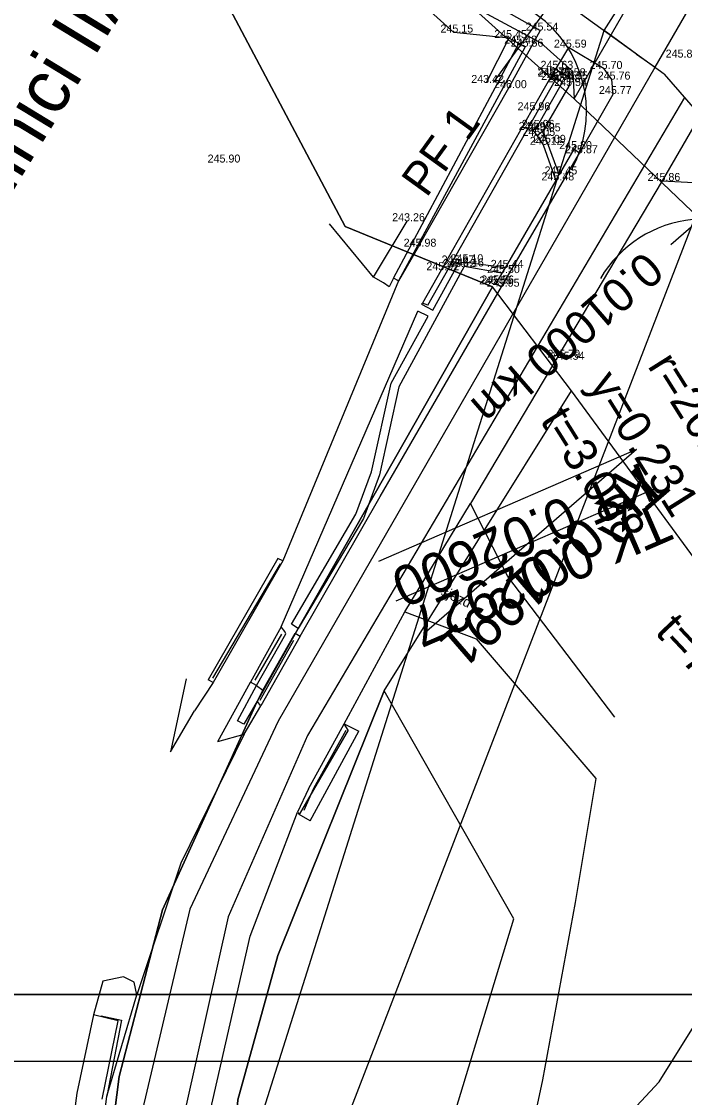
# Model space of a CAD drawing. Extents: x -555887 to -552101, y -1100251 to -1096546.
# Drawn here: x -554080.2 to -554030.5, y -1097398.4 to -1097317.8 of the extents above; entities that cross this region are included whole.
import ezdxf

# ---------------------------------------------------------------- set-up
doc = ezdxf.new("R2010")
doc.units = 0
for name, color, linetype in [('PARCELY_cesty', 7, 'Continuous'), ('PARCELY_silnice', 7, 'Continuous'), ('PARCELY_VHO', 7, 'Continuous'), ('POLYGONY_rozšíření', 7, 'Continuous'), ('POLYGONY_SITUACE_PF', 7, 'Continuous'), ('POLYGONY_SITUACE_PF_POPISY', 7, 'Continuous'), ('POLYGONY_SITUACE_PO', 7, 'Continuous'), ('ram_VC6', 7, 'Continuous'), ('ROZHLED_parcela_cesty', 7, 'Continuous'), ('ROZHLED_ram_legenda_1', 7, 'Continuous'), ('ROZHLED_ram_legenda_2', 7, 'Continuous'), ('ROZHLED_trojuhelniky_1', 7, 'Continuous'), ('ROZHLED_trojuhelniky_2', 7, 'Continuous'), ('vrstevnice', 7, 'Continuous'), ('Výškopis', 7, 'Continuous'), ('ZSST', 7, 'Continuous'), ('zájem', 7, 'Continuous')]:
    doc.layers.add(name, color=color, linetype=linetype)

msp = doc.modelspace()

# ---------------------------------------------------------------- linework, layer by layer
for p, q in [((-554034.06, -1097349.842), (-554053.407, -1097358.241)), ((-554034.06, -1097349.842), (-554050, -1097363.654)), ((-554032.76, -1097352.836), (-554052.107, -1097361.236))]:
    msp.add_line(p, q)
at = {"layer": 'PARCELY_cesty'}
msp.add_lwpolyline([(-554038.74, -1097323.54), (-554046.65, -1097316.45), (-554056.115, -1097302.24), (-554073.622, -1097267.292), (-554075.994, -1097261.695), (-554077.187, -1097257.67), (-554078.248, -1097251.684), (-554079.797, -1097235.406), (-554080.53, -1097230.23), (-554082.571, -1097222.628), (-554085.074, -1097216.125), (-554088.037, -1097210.809), (-554104.663, -1097183.794), (-554111.367, -1097172.04), (-554117.392, -1097160.013), (-554120.974, -1097151.787), (-554130.309, -1097129.113)], dxfattribs=at)
at = {"layer": 'PARCELY_silnice'}
msp.add_lwpolyline([(-553831.55, -1096945.97), (-553822.14, -1096946.52), (-553820.19, -1096947.25), (-553823.19, -1096962.08), (-553832.13, -1096986.8), (-553848.04, -1097015.24), (-554028.81, -1097333.03), (-554038.74, -1097323.54), (-553856.4, -1097007.66), (-553843.04, -1096981.51), (-553834.33, -1096958.81)], close=True, dxfattribs=at)
msp.add_lwpolyline([(-554030.91, -1097678.33), (-554047.02, -1097559.88), (-554049.28, -1097545.25), (-554058.01, -1097480.43), (-554064.42, -1097434.91), (-554064.99, -1097411.72), (-554063.97, -1097398.61), (-554060.96, -1097387.79), (-554052.99, -1097367.96), (-554038.93, -1097345.45), (-554044.87, -1097337.64), (-554059.66, -1097363.67), (-554062.54, -1097368.79), (-554069.61, -1097384.37), (-554072.86, -1097396.87), (-554074.7, -1097411.2), (-554074.25, -1097435.16), (-554067.74, -1097480.24), (-554068.8, -1097484.92), (-554059.78, -1097555.8), (-554058.52, -1097564.24), (-554053.21, -1097604.42), (-554046.53, -1097659.36)], dxfattribs=at)
at = {"layer": 'PARCELY_VHO'}
for points in [[(-553890.36, -1097670.23), (-553902.88, -1097642.35), (-553905.32, -1097611.67), (-553898.3, -1097524.98), (-553901.53, -1097506.94), (-553991.85, -1097382.83), (-554027.72, -1097360.75), (-554038.93, -1097345.45), (-554044.87, -1097337.64), (-554055.91, -1097333.12), (-554068.1, -1097310.12), (-554076.3, -1097297.37), (-554083.64, -1097283.44), (-554094.93, -1097256.14), (-554100.02, -1097244.94), (-554114.01, -1097204.34), (-554130.46, -1097180.06), (-554159.17, -1097101.34)], [(-554141.5, -1097107.04), (-554133.09, -1097133.96), (-554115.31, -1097177.28), (-554094.19, -1097204.11), (-554083.82, -1097222.99), (-554081.04, -1097249.03), (-554076.85, -1097264.17), (-554065.58, -1097288.03), (-554046.65, -1097316.45), (-554038.74, -1097323.54), (-554028.81, -1097333.03), (-554018.781, -1097341.326), (-554015.89, -1097351.24), (-554008.949, -1097355.38), (-553990.01, -1097365.499), (-553983.508, -1097370.361), (-553977.642, -1097376.021), (-553888.1, -1097498.254), (-553882.924, -1097507.258), (-553879.092, -1097522.388), (-553886.84, -1097615.05), (-553883.68, -1097641.57), (-553876.67, -1097669.5)], [(-553913.5, -1097649.75), (-553920.52, -1097625.16), (-553955.15, -1097551.67), (-553965.19, -1097535.15), (-553992.85, -1097506.35), (-554009.99, -1097493.12), (-554030.15, -1097490.89), (-554047.7, -1097471.03), (-554054.93, -1097432.75), (-554050.624, -1097409.22), (-554043.26, -1097385.04), (-554052.99, -1097367.96), (-554060.96, -1097387.79), (-554063.97, -1097398.61), (-554064.99, -1097411.72), (-554064.42, -1097434.91), (-554058.01, -1097480.43), (-554033.54, -1097499.24), (-554014.25, -1097501.88), (-553995.42, -1097511.01), (-553971.19, -1097536.91), (-553964.25, -1097552.71), (-553927.41, -1097628.08), (-553920.29, -1097651.1)]]:
    msp.add_lwpolyline(points, dxfattribs=at)
at = {"layer": 'POLYGONY_rozšíření'}
for centre, radius, start, end in [((-554046.785, -1097324.521), 8.976, 330.95257, 48.94424), ((-554028.999, -1097341.567), 9, 41.18214, 149.63339)]:
    msp.add_arc(centre, radius, start, end, dxfattribs=at)
at = {"layer": 'POLYGONY_SITUACE_PF'}
for p, q in [((-554044.776, -1097322.332), (-554040.095, -1097315.845)), ((-554025.436, -1097329.253), (-554031.482, -1097334.492))]:
    msp.add_line(p, q, dxfattribs=at)
at = {"layer": 'POLYGONY_SITUACE_PO'}
for p, q in [((-554040.89, -1097317.753), (-554043.003, -1097316.139)), ((-554031.985, -1097321.695), (-554040.093, -1097315.846)), ((-554031.985, -1097321.695), (-554018.945, -1097336.744))]:
    msp.add_line(p, q, dxfattribs=at)
at = {"layer": 'ram_VC6'}
for points in [[(-553956.64, -1096765.72), (-554313.64, -1096765.72), (-554313.64, -1097395.72), (-553956.64, -1097395.72)], [(-553961.64, -1096770.72), (-554308.64, -1096770.72), (-554308.64, -1097390.72), (-553961.64, -1097390.72)]]:
    msp.add_lwpolyline(points, close=True, dxfattribs=at)
for points in [[(-553956.64, -1096765.72), (-554313.64, -1096765.72), (-554313.64, -1097395.72), (-553956.64, -1097395.72), (-553956.64, -1096765.72)], [(-553956.64, -1096765.72), (-554313.64, -1096765.72), (-554313.64, -1097395.72), (-553956.64, -1097395.72), (-553956.64, -1096765.72)], [(-553961.64, -1097390.72), (-554308.64, -1097390.72), (-554308.64, -1096770.72), (-553961.64, -1096770.72), (-553961.64, -1097390.72)], [(-553961.64, -1097185.72), (-553961.64, -1097390.72), (-554308.64, -1097390.72), (-554308.64, -1096770.72), (-553961.64, -1096770.72), (-553961.64, -1096975.72), (-553961.64, -1097185.72)]]:
    msp.add_lwpolyline(points, dxfattribs=at)
at = {"layer": 'ROZHLED_parcela_cesty'}
msp.add_lwpolyline([(-554065.58, -1097288.03), (-554046.65, -1097316.45), (-554041.23, -1097319.36), (-554038.83, -1097321.49), (-554038.74, -1097323.54), (-554032.65, -1097312.99), (-554038, -1097312.7), (-554047.82, -1097302.49), (-554048.47, -1097299.87), (-554057.99, -1097283.5)], dxfattribs=at)
at = {"layer": 'ROZHLED_trojuhelniky_1'}
for p, q in [((-554036.491, -1097318.429), (-553972.591, -1097217.302)), ((-554032.67, -1097321.18), (-553972.591, -1097217.302)), ((-554072.18, -1097431.536), (-554036.491, -1097318.429)), ((-554034.07, -1097320.2), (-554036.491, -1097318.429)), ((-554034.07, -1097320.2), (-554032.67, -1097321.18))]:
    msp.add_line(p, q, dxfattribs=at)
msp.add_lwpolyline([(-554032.679, -1097321.195), (-554060.95, -1097370.23), (-554067.57, -1097384.31), (-554072.85, -1097406.639), (-554072.182, -1097431.541)], dxfattribs=at)
at = {"layer": 'ROZHLED_trojuhelniky_2'}
msp.add_line((-554068.929, -1097434.118), (-554027.513, -1097326.846), dxfattribs=at)
msp.add_lwpolyline([(-554030.465, -1097323.449), (-554058.75, -1097371.31), (-554064.7, -1097384.89), (-554069.39, -1097405.96), (-554068.929, -1097434.118)], dxfattribs=at)
at = {"layer": 'vrstevnice'}
msp.add_lwpolyline([(-554190.329, -1097523.08), (-554168.989, -1097521.25), (-554159.999, -1097519.71), (-554148.909, -1097516.2), (-554142.869, -1097513.11), (-554135.289, -1097507.77), (-554123.069, -1097495.14), (-554117.169, -1097487.41), (-554094.989, -1097453.71), (-554083.889, -1097438.27), (-554078.139, -1097431.53), (-554073.499, -1097427.46), (-554061.289, -1097425.77), (-554055.949, -1097419.59), (-554038.119, -1097403.45), (-554032.359, -1097397.27), (-554025.339, -1097386.03), (-554021.07, -1097375.17)], dxfattribs=at)
at = {"layer": 'ZSST'}
for p, q in [((-554041.57, -1097325.73), (-554041.84, -1097325.89)), ((-554041.1, -1097325.99), (-554041.51, -1097326.33)), ((-554053.78, -1097336.92), (-554057.1, -1097332.92)), ((-554044.16, -1097336.62), (-554046.99, -1097336.12)), ((-554051.91, -1097337.2), (-554060.58, -1097358.21)), ((-554060.71, -1097363.16), (-554050.46, -1097339.48)), ((-554049.72, -1097339.03), (-554050.12, -1097338.87)), ((-554039.32, -1097343.12), (-554039.67, -1097342.97)), ((-554060.96, -1097358.02), (-554066.184, -1097367.121)), ((-554060.96, -1097358.02), (-554066.184, -1097367.121)), ((-554060.58, -1097358.21), (-554060.96, -1097358.02)), ((-554060.96, -1097358.02), (-554060.96, -1097358.02)), ((-554065.83, -1097366.99), (-554060.76, -1097358.42)), ((-554060.58, -1097358.21), (-554065.82, -1097367.33)), ((-554061.166, -1097358.387), (-554061.166, -1097358.387)), ((-554060.71, -1097363.16), (-554063.01, -1097367.31)), ((-554060.7, -1097363.71), (-554062.7, -1097367.16)), ((-554062.08, -1097367.9), (-554059.66, -1097363.63)), ((-554062.3, -1097368.64), (-554059.76, -1097364.15)), ((-554065.82, -1097367.33), (-554067.21, -1097369.46)), ((-554065.82, -1097367.33), (-554066.184, -1097367.121)), ((-554065.47, -1097371.74), (-554063.01, -1097367.31)), ((-554062.57, -1097367.54), (-554063.01, -1097367.31)), ((-554063.48, -1097371.19), (-554062.25, -1097369.08)), ((-554055.69, -1097370.89), (-554059.36, -1097377.22)), ((-554058.55, -1097377.69), (-554054.9, -1097370.97)), ((-554055.69, -1097370.89), (-554056, -1097370.43)), ((-554065.47, -1097371.74), (-554063.48, -1097371.19)), ((-554065.47, -1097371.74), (-554065.47, -1097371.74)), ((-554063.48, -1097371.19), (-554063.48, -1097371.19)), ((-554058.55, -1097377.69), (-554059.36, -1097377.22)), ((-554073.79, -1097398.34), (-554073.79, -1097398.34))]:
    msp.add_line(p, q, dxfattribs=at)
for points in [[(-553831.64, -1096923.82), (-553835.69, -1096943.09), (-553842.4, -1096966.86), (-553850.34, -1096985.69), (-553856.05, -1096996.17), (-553876.09, -1097031.09), (-553900.82, -1097073.95), (-553925.65, -1097117.01), (-553973.36, -1097200.46), (-553998.81, -1097244.48), (-554018.03, -1097278.18), (-554032.06, -1097302.7), (-554039.09, -1097314.61), (-554042.48, -1097312.42), (-554044.85, -1097316.43), (-554041.28, -1097318.43), (-554043.66, -1097322.75), (-554050.44, -1097334.64), (-554051.91, -1097337.2)], [(-553818.18, -1096926.71), (-553821.78, -1096945.09), (-553822.5, -1096948.29), (-553824.54, -1096956.94), (-553827.64, -1096967.4), (-553833.07, -1096981.13), (-553839.89, -1096995.89), (-553855.52, -1097024.97), (-553869.86, -1097050.06), (-553885.29, -1097076.39), (-553900.2, -1097101.88), (-553913.69, -1097125.22), (-553931.8, -1097156.33), (-553935.29, -1097162.25), (-553959.78, -1097204.54), (-553977.15, -1097234.71), (-553995.37, -1097266.5), (-554014.37, -1097299.01), (-554027.49, -1097321.67), (-554032.14, -1097329.71), (-554046.52, -1097353.89)], [(-554043.64, -1097319), (-554047.77, -1097318.58), (-554052.74, -1097314.07), (-554056.9, -1097304), (-554062.41, -1097287), (-554068.66, -1097272.27), (-554076.19, -1097251.39), (-554079.41, -1097237.5), (-554082.27, -1097222.72), (-554086.75, -1097212.07), (-554091.28, -1097204.32), (-554100.2, -1097193.1), (-554110.38, -1097176.19), (-554116.77, -1097164.16), (-554127.72, -1097139.75), (-554132.59, -1097127.58)], [(-554042.89, -1097319.41), (-554043.64, -1097319), (-554045.34, -1097322.36)], [(-554038.34, -1097327.63), (-554035.82, -1097323.19), (-554035.9, -1097322.11), (-554036.49, -1097321.31), (-554039.16, -1097319.71), (-554040.49, -1097321.9)], [(-554041.57, -1097325.73), (-554039.62, -1097322.31), (-554040.42, -1097321.8)], [(-554040.15, -1097321.3), (-554039.23, -1097321.86), (-554039.05, -1097322.1), (-554039.14, -1097322.59), (-554041.1, -1097325.99)], [(-554040.49, -1097321.9), (-554041.9, -1097324.41), (-554048.72, -1097336.41), (-554050.12, -1097338.87), (-554050.2, -1097338.96), (-554049.35, -1097339.41)], [(-554049.72, -1097339.03), (-554040.13, -1097322.13), (-554040.49, -1097321.9)], [(-554041.84, -1097325.89), (-554041.51, -1097326.33), (-554041.06, -1097327), (-554040.1, -1097329.67), (-554039.86, -1097329.22)], [(-554044.19, -1097337.64), (-554038.34, -1097327.63), (-554038.76, -1097327.32), (-554039.86, -1097329.22), (-554040.73, -1097326.85), (-554041.1, -1097325.99)], [(-554040.1, -1097329.67), (-554043.91, -1097336.23), (-554047.02, -1097335.81)], [(-554032.14, -1097329.71), (-554028.82, -1097329.87), (-554025.45, -1097333.46), (-554020.91, -1097340.19)], [(-554052.28, -1097336.99), (-554052.61, -1097337.65), (-554053.05, -1097337.34), (-554053.78, -1097336.92), (-554051.27, -1097332.73)], [(-554049.35, -1097339.41), (-554047.57, -1097336.17), (-554047.6, -1097335.9), (-554047.02, -1097335.81), (-554046.99, -1097336.12), (-554051.89, -1097345.16), (-554053.35, -1097351.74), (-554054.55, -1097355.03), (-554059.43, -1097363.27), (-554059.95, -1097362.95)], [(-554043.91, -1097336.23), (-554044.16, -1097336.62), (-554044.61, -1097337.4), (-554044.19, -1097337.64)], [(-554059.28, -1097363.85), (-554053.29, -1097353.38), (-554044.19, -1097337.64)], [(-554059.95, -1097362.95), (-554055.11, -1097354.71), (-554053.95, -1097351.52), (-554052.46, -1097344.88), (-554049.7, -1097339.86), (-554050.46, -1097339.48)], [(-554056, -1097370.43), (-554051.44, -1097362.02), (-554046.52, -1097353.89)], [(-554035.68, -1097369.92), (-554043.72, -1097359.38), (-554046.52, -1097353.89)], [(-554051.44, -1097362.02), (-554046.1, -1097364.05), (-554037.12, -1097374.53)], [(-554062.57, -1097367.54), (-554060.37, -1097363.68), (-554060.45, -1097363.5), (-554060.71, -1097363.16)], [(-554059.66, -1097363.63), (-554059.28, -1097363.85), (-554062.25, -1097369.08), (-554062.52, -1097368.73)], [(-554067.84, -1097367.06), (-554069.01, -1097372.53), (-554067.21, -1097369.46)], [(-554059, -1097376.91), (-554058.26, -1097375.24), (-554055.84, -1097370.89)], [(-554058.66, -1097375.29), (-554056, -1097370.43), (-554054.9, -1097370.97)], [(-554063.48, -1097371.19), (-554068.25, -1097380.88), (-554071.53, -1097390.75)], [(-554037.12, -1097374.53), (-554038.66, -1097383.83), (-554041.11, -1097397.12)], [(-554058.66, -1097375.29), (-554059.5, -1097377.06), (-554059.36, -1097377.22)], [(-554052.25, -1097540.48), (-554066.88, -1097439.41), (-554068.04, -1097416.49), (-554067.01, -1097403.76), (-554063.04, -1097386.34), (-554059.5, -1097377.06)], [(-554071.53, -1097390.75), (-554071.75, -1097389.79), (-554072.54, -1097389.39), (-554074.08, -1097389.71), (-554074.78, -1097392.24), (-554076.03, -1097398.13), (-554076.57, -1097402.1), (-554076.89, -1097407.48), (-554076.29, -1097419.66), (-554075.23, -1097429.16), (-554074.15, -1097435.11)], [(-554074.79, -1097419.98), (-554074.94, -1097407.92), (-554073.79, -1097398.34), (-554071.53, -1097390.75)], [(-554074.14, -1097398.57), (-554072.93, -1097392.69), (-554074.78, -1097392.24)], [(-554074.22, -1097392.33), (-554072.7, -1097392.65), (-554073.79, -1097398.34)], [(-554041.11, -1097397.12), (-554044.32, -1097412.11), (-554048.01, -1097427.93), (-554050.67, -1097444.04), (-554048.27, -1097459.6), (-554042, -1097470.14), (-554037.74, -1097478.62), (-554033.95, -1097486.93), (-554027.65, -1097493.26), (-554019.52, -1097492), (-554008.89, -1097493.27), (-554003.64, -1097496.63), (-553994.28, -1097505.16), (-553985.02, -1097510.4), (-553975.58, -1097519.29), (-553972.07, -1097524.68), (-553966.56, -1097533.56), (-553961.13, -1097544.92), (-553948.08, -1097565.91), (-553939.6, -1097584.69), (-553931.83, -1097597.83), (-553917.93, -1097595.69)]]:
    msp.add_lwpolyline(points, dxfattribs=at)
for points in [[(-554051.91, -1097337.2), (-554052.28, -1097336.99), (-554042.89, -1097319.41), (-554042.4, -1097319.64)], [(-554063.52, -1097370.46), (-554064, -1097370.19), (-554062.57, -1097367.54), (-554062.08, -1097367.9), (-554062.52, -1097368.73)]]:
    msp.add_lwpolyline(points, close=True, dxfattribs=at)
at = {"layer": 'zájem'}
for points in [[(-554209.05, -1097338.04), (-554121.59, -1097427.95), (-554119.85, -1097429.74), (-554117.62, -1097427.68), (-554074.61, -1097473), (-554067.74, -1097480.24), (-554074.25, -1097435.16), (-554074.7, -1097411.2), (-554072.86, -1097396.87), (-554069.61, -1097384.37), (-554062.54, -1097368.79), (-554059.66, -1097363.67), (-554044.87, -1097337.64), (-554055.91, -1097333.12), (-554068.1, -1097310.12), (-554076.3, -1097297.37), (-554083.64, -1097283.44), (-554094.93, -1097256.14), (-554100.02, -1097244.94), (-554114.01, -1097204.34), (-554130.46, -1097180.06), (-554159.17, -1097101.34)], [(-554159.17, -1097101.34), (-554130.46, -1097180.06), (-554114.01, -1097204.34), (-554100.02, -1097244.94), (-554094.93, -1097256.14), (-554083.64, -1097283.44), (-554076.3, -1097297.37), (-554068.1, -1097310.12), (-554055.91, -1097333.12), (-554044.87, -1097337.64), (-554059.66, -1097363.67), (-554062.54, -1097368.79), (-554069.61, -1097384.37), (-554072.86, -1097396.87), (-554074.7, -1097411.2), (-554074.25, -1097435.16), (-554067.74, -1097480.24), (-554074.61, -1097473), (-554117.62, -1097427.68), (-554119.85, -1097429.74), (-554121.59, -1097427.95), (-554209.05, -1097338.04)]]:
    msp.add_lwpolyline(points, dxfattribs=at)

# ---------------------------------------------------------------- texts
for s, height, rotation, p in [('r=20.0', 2.5, 302.1889, (-554033.277, -1097343.577)), ('y=0.231', 2.5, 302.1889, (-554037.72, -1097344.965)), ('t=3.068', 2.5, 302.1889, (-554041.344, -1097347.655)), ('KT 0.02600', 3, 203.46787, (-554033.661, -1097350.759)), ('TK 0.01991', 3, 220.90993, (-554033.405, -1097350.597)), ('TK 0.02927', 3, 203.46787, (-554032.361, -1097353.753)), ('t=7.209', 2.5, 313.28926, (-554032.753, -1097363.591))]:
    msp.add_text(s, height=height, rotation=rotation).set_placement(p)
at = {"layer": 'POLYGONY_SITUACE_PF_POPISY'}
for s, rotation, p in [('PF 1', 54.18791, (-554049.816, -1097331.027)), ('0.01000 km', 220.90993, (-554033.462, -1097334.884))]:
    msp.add_text(s, height=2.5, rotation=rotation, dxfattribs=at).set_placement(p)
at = {"layer": 'ROZHLED_ram_legenda_1'}
msp.add_text('Státní pozemkový úřad, Krajský pozemkový úřad pro', height=2, rotation=241.51269, dxfattribs=at).set_placement((-554075.872, -1097271.769))
at = {"layer": 'ROZHLED_ram_legenda_2'}
msp.add_text('Rozhledové poměry - napojení DC4 na  silnici II/446', height=4, rotation=58.6856, dxfattribs=at).set_placement((-554131.926, -1097414.479))
at = {"layer": 'Výškopis'}
for s, p in [('245.54', (-554042.376, -1097318.43)), ('245.15', (-554048.764, -1097318.58)), ('245.45', (-554044.736, -1097319)), ('245.48', (-554043.978, -1097319.41)), ('245.56', (-554043.496, -1097319.64)), ('245.59', (-554040.256, -1097319.71)), ('245.85', (-554031.874, -1097320.46)), ('245.63', (-554041.258, -1097321.3)), ('245.70', (-554037.569, -1097321.31)), ('243.42', (-554046.456, -1097322.36)), ('245.70', (-554041.499, -1097321.8)), ('245.71', (-554041.458, -1097321.9)), ('245.64', (-554041.213, -1097322.13)), ('245.58', (-554040.722, -1097322.31)), ('245.58', (-554040.332, -1097321.86)), ('245.55', (-554040.16, -1097322.1)), ('245.76', (-554036.971, -1097322.11)), ('246.00', (-554044.745, -1097322.75)), ('245.54', (-554040.236, -1097322.59)), ('245.77', (-554036.879, -1097323.19)), ('245.96', (-554042.983, -1097324.41)), ('245.06', (-554042.66, -1097325.73)), ('244.97', (-554042.897, -1097325.89)), ('245.05', (-554042.614, -1097326.33)), ('245.05', (-554042.204, -1097325.99)), ('245.12', (-554042.062, -1097327)), ('245.09', (-554041.82, -1097326.85)), ('245.80', (-554039.858, -1097327.32)), ('245.87', (-554039.419, -1097327.63)), ('245.90', (-554066.23, -1097328.33)), ('245.48', (-554041.188, -1097329.67)), ('245.45', (-554040.956, -1097329.22)), ('245.86', (-554033.23, -1097329.71)), ('243.26', (-554052.386, -1097332.73)), ('245.98', (-554051.528, -1097334.64)), ('245.07', (-554048.679, -1097335.9)), ('245.12', (-554048.572, -1097336.17)), ('245.10', (-554048.008, -1097335.81)), ('245.16', (-554047.97, -1097336.12)), ('245.92', (-554049.824, -1097336.41)), ('245.50', (-554045.264, -1097336.62)), ('245.44', (-554044.993, -1097336.23)), ('245.55', (-554045.86, -1097337.47)), ('245.56', (-554045.706, -1097337.4)), ('245.95', (-554045.286, -1097337.64)), ('245.79', (-554040.741, -1097342.97)), ('245.54', (-554040.416, -1097343.12))]:
    msp.add_text(s, height=0.6, dxfattribs=at).set_placement(p)
at = {"layer": 'ZSST'}
msp.add_text('sjezd', height=0.75, rotation=334.60735, dxfattribs=at).set_placement((-554048.791, -1097360.744))

doc.saveas('drawing.dxf')
